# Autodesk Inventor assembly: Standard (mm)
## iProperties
Part Number: Standard (mm)
Document SubType Name: Assembly
Control State: 0
Master: False
Checked Out: False
PropertySet Name: Design Tracking Control
Shininess: 64.0
Angle Display Precision: 2
Document Length Units: 11269
Document Angle Units: 11283
Document Time Units: 11279
Document Mass Units: 11290
Document Length Units Precision: 3
Document Angle Units Precision: 2
Compacted: True
PropertySet Name: _Private Model Information
Density: 0.0
Volumn: 0.0
Area: 0.0
PropertySet Name: Model Information
